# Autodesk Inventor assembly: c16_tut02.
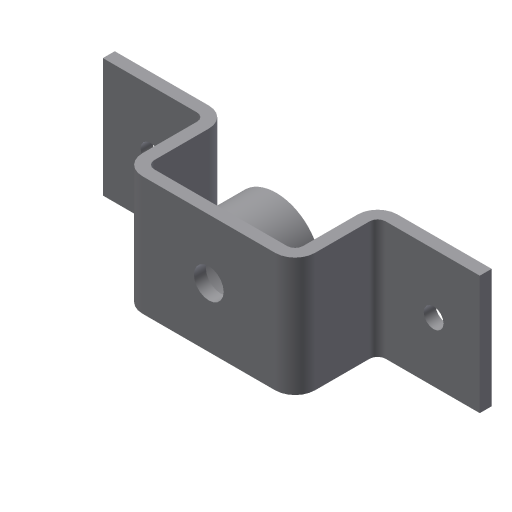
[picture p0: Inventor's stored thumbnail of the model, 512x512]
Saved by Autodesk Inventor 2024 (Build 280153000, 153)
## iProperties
Created: 2010-05
Part Number: c16_tut02.
Document SubType Name: Weldment
Designer: CADSoft
Weld Material: Welded Aluminum-6061
Author: CADSoft
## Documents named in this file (3)
- D:\PROJECTS\Project 2023\RESOURCES INVENTOR 2024\RESOURCES INVENTOR 2024\Inventor_2024_tut\Inventor_2024_tut\c16_Inv_2024_tut\c16_Inv_tut_2024\c16_tut02\c16_tut02..iam
- D:\PROJECTS\Project 2023\RESOURCES INVENTOR 2024\RESOURCES INVENTOR 2024\Inventor_2024_tut\Inventor_2024_tut\c16_Inv_2024_tut\c16_Inv_tut_2024\c16_tut02\Bracket.ipt
- D:\PROJECTS\Project 2023\RESOURCES INVENTOR 2024\RESOURCES INVENTOR 2024\Inventor_2024_tut\Inventor_2024_tut\c16_Inv_2024_tut\c16_Inv_tut_2024\c16_tut02\Cylinder.ipt
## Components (2 placed, 2 different names)
1. Bracket:1 — Mate:1, Mate:2
2. Cylinder:1 — Mate:1, Mate:2
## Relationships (2: Mate 2)
- Mate:1: Bracket:1 ↔ Cylinder:1
- Mate:2: Bracket:1 ↔ Cylinder:1
